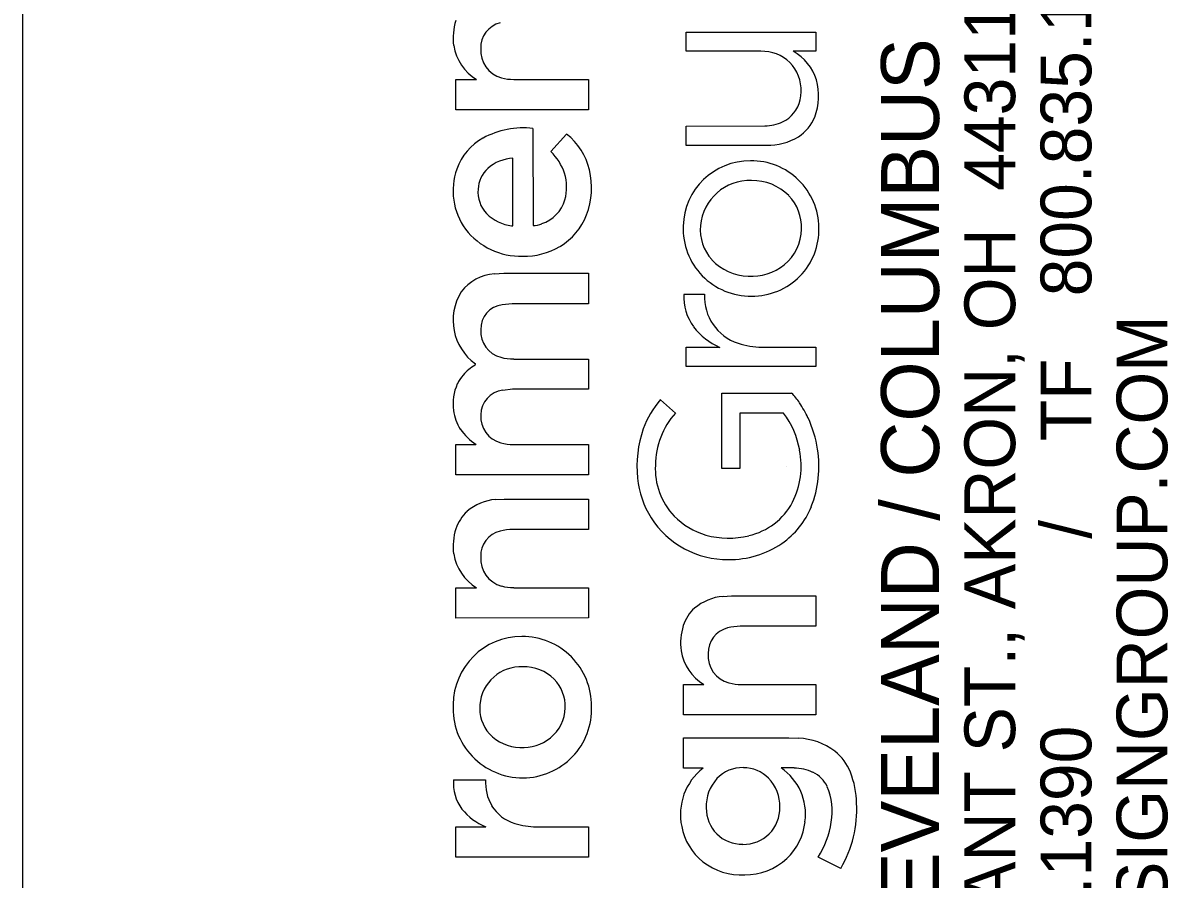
# Model space of a CAD drawing. Extents: x -4.2 to 34, y 0 to 22.
# Drawn here: x 32 to 33.125, y 3.594 to 4.436 of the extents above; entities that cross this region are included whole.
import ezdxf

# ---------------------------------------------------------------- set-up
doc = ezdxf.new("R2010")
doc.units = 0
doc.layers.add('SH_Border', color=7, linetype='Continuous')
doc.layers.add('SH_Data', color=7, linetype='Continuous')

msp = doc.modelspace()

# ---------------------------------------------------------------- linework, layer by layer
at = {"layer": 'SH_Border'}
msp.add_line((32, 0.5), (32, 21.5), dxfattribs=at)
at = {"layer": 'SH_Data'}
for p, q in [((32.6515, 4.408), (32.6515, 4.4267)), ((32.6515, 4.4267), (32.7791, 4.4266)), ((32.7791, 4.4266), (32.7791, 4.408)), ((32.7249, 4.408), (32.6515, 4.408)), ((32.7328, 4.4073), (32.7249, 4.408)), ((32.7791, 4.408), (32.7569, 4.408)), ((32.4254, 4.3503), (32.4254, 4.3802)), ((32.4254, 4.3802), (32.4455, 4.3802)), ((32.4822, 4.3802), (32.5557, 4.3802)), ((32.5557, 4.3802), (32.5557, 4.3504)), ((32.5557, 4.3504), (32.4254, 4.3503)), ((32.5011, 4.3321), (32.5012, 4.2366)), ((32.6515, 4.3344), (32.7291, 4.3345)), ((32.6517, 4.3154), (32.6515, 4.3344)), ((32.5188, 4.3093), (32.5342, 4.3266)), ((32.7307, 4.3154), (32.6517, 4.3154)), ((32.4814, 4.2364), (32.4814, 4.303)), ((32.4802, 4.2363), (32.4814, 4.2364)), ((32.4633, 4.1891), (32.4726, 4.1897)), ((32.4726, 4.1897), (32.5556, 4.1897)), ((32.5556, 4.1897), (32.5557, 4.1598)), ((32.6493, 4.1691), (32.6698, 4.1691)), ((32.4806, 4.1598), (32.471, 4.1588)), ((32.5557, 4.1598), (32.4806, 4.1598)), ((32.6515, 4.098), (32.6515, 4.117)), ((32.6515, 4.117), (32.6848, 4.117)), ((32.726, 4.117), (32.7791, 4.117)), ((32.7791, 4.117), (32.779, 4.098)), ((32.4444, 4.0992), (32.4446, 4.1007)), ((32.4822, 4.1055), (32.5557, 4.1055)), ((32.5557, 4.1055), (32.5557, 4.0757)), ((32.779, 4.098), (32.6515, 4.098)), ((32.4809, 4.0757), (32.4714, 4.0747)), ((32.5557, 4.0757), (32.4809, 4.0757)), ((32.6264, 4.0655), (32.6411, 4.0524)), ((32.6868, 4.0718), (32.7552, 4.0719)), ((32.6868, 3.9978), (32.6868, 4.0718)), ((32.7045, 4.0524), (32.7043, 3.9978)), ((32.7474, 4.0523), (32.7045, 4.0524)), ((32.4254, 3.9915), (32.4254, 4.0214)), ((32.4254, 4.0214), (32.4451, 4.0214)), ((32.4821, 4.0214), (32.5557, 4.0214)), ((32.5557, 4.0214), (32.5557, 3.9916)), ((32.7043, 3.9978), (32.6868, 3.9978)), ((32.75, 4), (32.75, 4)), ((32.5557, 3.9916), (32.4254, 3.9915)), ((32.4644, 3.9674), (32.4729, 3.9678)), ((32.4729, 3.9678), (32.5557, 3.9678)), ((32.5557, 3.9678), (32.5557, 3.938)), ((32.5557, 3.938), (32.4814, 3.938)), ((32.4254, 3.8509), (32.4254, 3.8807)), ((32.4254, 3.8807), (32.4455, 3.8807)), ((32.4822, 3.8807), (32.5557, 3.8807)), ((32.5557, 3.8807), (32.5557, 3.851)), ((32.6878, 3.8722), (32.6963, 3.8727)), ((32.6963, 3.8727), (32.7792, 3.8727)), ((32.7792, 3.8727), (32.7792, 3.8429)), ((32.5557, 3.851), (32.4254, 3.8509)), ((32.7792, 3.8429), (32.7048, 3.8428)), ((32.6489, 3.7557), (32.6489, 3.7855)), ((32.6489, 3.7855), (32.669, 3.7855)), ((32.7057, 3.7855), (32.7791, 3.7855)), ((32.7791, 3.7855), (32.7792, 3.7558)), ((32.7792, 3.7558), (32.6489, 3.7557)), ((32.6489, 3.7034), (32.6489, 3.7332)), ((32.6489, 3.7332), (32.7524, 3.7332)), ((32.7524, 3.7332), (32.7619, 3.7329)), ((32.6684, 3.7034), (32.6489, 3.7034)), ((32.7576, 3.7036), (32.7449, 3.7036)), ((32.423, 3.6919), (32.4545, 3.6919)), ((32.4254, 3.6159), (32.4254, 3.6458)), ((32.4254, 3.6458), (32.4547, 3.6458)), ((32.5041, 3.6458), (32.5557, 3.6457)), ((32.5557, 3.6457), (32.5556, 3.6159)), ((32.5556, 3.6159), (32.4254, 3.6159)), ((32.8036, 3.6049), (32.7812, 3.616))]:
    msp.add_line(p, q, dxfattribs=at)
for points in [[(32.7328, 4.4073), (32.7249, 4.408), (32.6515, 4.408), (32.6515, 4.4267), (32.7791, 4.4266), (32.7791, 4.408), (32.7569, 4.408)], [(32.4254, 4.3503), (32.4254, 4.3802), (32.4455, 4.3802)], [(32.4822, 4.3802), (32.5557, 4.3802), (32.5557, 4.3504), (32.4254, 4.3503)], [(32.5011, 4.3321), (32.5012, 4.2366)], [(32.7307, 4.3154), (32.6517, 4.3154), (32.6515, 4.3344), (32.7291, 4.3345)], [(32.5188, 4.3093), (32.5342, 4.3266)], [(32.4802, 4.2363), (32.4814, 4.2364), (32.4814, 4.303)], [(32.4633, 4.1891), (32.4726, 4.1897), (32.5556, 4.1897), (32.5557, 4.1598), (32.4806, 4.1598), (32.471, 4.1588)], [(32.6493, 4.1691), (32.6698, 4.1691)], [(32.6515, 4.098), (32.6515, 4.117), (32.6848, 4.117)], [(32.726, 4.117), (32.7791, 4.117), (32.779, 4.098), (32.6515, 4.098)], [(32.4444, 4.0992), (32.4446, 4.1007)], [(32.4822, 4.1055), (32.5557, 4.1055), (32.5557, 4.0757), (32.4809, 4.0757), (32.4714, 4.0747)], [(32.6264, 4.0655), (32.6411, 4.0524)], [(32.7474, 4.0523), (32.7045, 4.0524), (32.7043, 3.9978), (32.6868, 3.9978), (32.6868, 4.0718), (32.7552, 4.0719)], [(32.4254, 3.9915), (32.4254, 4.0214), (32.4451, 4.0214)], [(32.4821, 4.0214), (32.5557, 4.0214), (32.5557, 3.9916), (32.4254, 3.9915)], [(32.4644, 3.9674), (32.4729, 3.9678), (32.5557, 3.9678), (32.5557, 3.938), (32.4814, 3.938)], [(32.4254, 3.8509), (32.4254, 3.8807), (32.4455, 3.8807)], [(32.4822, 3.8807), (32.5557, 3.8807), (32.5557, 3.851), (32.4254, 3.8509)], [(32.6878, 3.8722), (32.6963, 3.8727), (32.7792, 3.8727), (32.7792, 3.8429), (32.7048, 3.8428)], [(32.6489, 3.7557), (32.6489, 3.7855), (32.669, 3.7855)], [(32.7057, 3.7855), (32.7791, 3.7855), (32.7792, 3.7558), (32.6489, 3.7557)], [(32.6684, 3.7034), (32.6489, 3.7034), (32.6489, 3.7332), (32.7524, 3.7332), (32.7619, 3.7329)], [(32.7576, 3.7036), (32.7449, 3.7036)], [(32.423, 3.6919), (32.4545, 3.6919)], [(32.4254, 3.6159), (32.4254, 3.6458), (32.4547, 3.6458)], [(32.5041, 3.6458), (32.5557, 3.6457), (32.5556, 3.6159), (32.4254, 3.6159)], [(32.8036, 3.6049), (32.7812, 3.616)]]:
    msp.add_lwpolyline(points, dxfattribs=at)
for centre, radius, start, end in [((32.4787, 4.4211), 0.056, 162.274, 187.7917), ((32.4787, 4.4211), 0.056, 162.274, 187.7917), ((32.4748, 4.4116), 0.025, 103.6868, 182.214), ((32.4748, 4.4116), 0.025, 103.6868, 182.214), ((32.4703, 4.4209), 0.0476, 188.9646, 238.6987), ((32.4703, 4.4209), 0.0476, 188.9646, 238.6987), ((32.4774, 4.4085), 0.0276, 175.5844, 255.1382), ((32.4774, 4.4085), 0.0276, 175.5844, 255.1382), ((32.7271, 4.37), 0.0377, 33.5008, 81.3295), ((32.7271, 4.37), 0.0377, 33.5008, 81.3295), ((32.7324, 4.3648), 0.0496, 17.6221, 60.3897), ((32.7324, 4.3648), 0.0496, 17.6221, 60.3897), ((32.7241, 4.3695), 0.0405, 346.5618, 31.7539), ((32.7241, 4.3695), 0.0405, 346.5618, 31.7539), ((32.4818, 4.4224), 0.0421, 254.0891, 270.5284), ((32.4818, 4.4224), 0.0421, 254.0891, 270.5284), ((32.7234, 4.3641), 0.0584, 339.162, 15.6148), ((32.7234, 4.3641), 0.0584, 339.162, 15.6148), ((32.7337, 4.3662), 0.0304, 294.6321, 348.4863), ((32.7337, 4.3662), 0.0304, 294.6321, 348.4863), ((32.739, 4.359), 0.042, 303.1039, 338.1561), ((32.739, 4.359), 0.042, 303.1039, 338.1561), ((32.4918, 4.2487), 0.0839, 83.6212, 118.2845), ((32.4918, 4.2487), 0.0839, 83.6212, 118.2845), ((32.7275, 4.3808), 0.0463, 271.952, 294.0894), ((32.7275, 4.3808), 0.0463, 271.952, 294.0894), ((32.4789, 4.2737), 0.0558, 118.8294, 160.6224), ((32.4789, 4.2737), 0.0558, 118.8294, 160.6224), ((32.494, 4.2763), 0.0644, 13.5328, 51.3627), ((32.494, 4.2763), 0.0644, 13.5328, 51.3627), ((32.7321, 4.3726), 0.0571, 268.627, 301.4778), ((32.7321, 4.3726), 0.0571, 268.627, 301.4778), ((32.4803, 4.2702), 0.0549, 19.0387, 45.4432), ((32.4803, 4.2702), 0.0549, 19.0387, 45.4432), ((32.4844, 4.2607), 0.0424, 94.0131, 130.8806), ((32.4844, 4.2607), 0.0424, 94.0131, 130.8806), ((32.7143, 4.2348), 0.0655, 89.4821, 178.7775), ((32.7143, 4.2348), 0.0655, 89.4821, 178.7775), ((32.7158, 4.2341), 0.0662, 0.4227, 90.7613), ((32.7158, 4.2341), 0.0662, 0.4227, 90.7613), ((32.487, 4.2707), 0.0644, 160.5214, 215.7815), ((32.487, 4.2707), 0.0644, 160.5214, 215.7815), ((32.477, 4.2709), 0.0298, 132.9855, 177.1802), ((32.477, 4.2709), 0.0298, 132.9855, 177.1802), ((32.4872, 4.2743), 0.047, 344.6072, 17.0067), ((32.4872, 4.2743), 0.047, 344.6072, 17.0067), ((32.4829, 4.2738), 0.0758, 339.3543, 13.3771), ((32.4829, 4.2738), 0.0758, 339.3543, 13.3771), ((32.714, 4.2324), 0.0485, 87.6883, 175.017), ((32.714, 4.2324), 0.0485, 87.6883, 175.017), ((32.7166, 4.2304), 0.0505, 44.912, 90.7591), ((32.7166, 4.2304), 0.0505, 44.912, 90.7591), ((32.4782, 4.2697), 0.0311, 175.0014, 223.2876), ((32.4782, 4.2697), 0.0311, 175.0014, 223.2876), ((32.7196, 4.2345), 0.0455, 358.3228, 43.8349), ((32.7196, 4.2345), 0.0455, 358.3228, 43.8349), ((32.499, 4.2718), 0.035, 288.0108, 343.5536), ((32.499, 4.2718), 0.035, 288.0108, 343.5536), ((32.4855, 4.2783), 0.0423, 225.0645, 262.797), ((32.4855, 4.2783), 0.0423, 225.0645, 262.797), ((32.4955, 4.2698), 0.0626, 300.9439, 338.7322), ((32.4955, 4.2698), 0.0626, 300.9439, 338.7322), ((32.4891, 4.2752), 0.0687, 217.7434, 271.6561), ((32.4891, 4.2752), 0.0687, 217.7434, 271.6561), ((32.5013, 4.2568), 0.0202, 269.7004, 294.8729), ((32.5013, 4.2568), 0.0202, 269.7004, 294.8729), ((32.7148, 4.2334), 0.0661, 177.5373, 270.9452), ((32.7148, 4.2334), 0.0661, 177.5373, 270.9452), ((32.7108, 4.2331), 0.0453, 175.5147, 221.4205), ((32.7108, 4.2331), 0.0453, 175.5147, 221.4205), ((32.7167, 4.2327), 0.0654, 269.3083, 1.6791), ((32.7167, 4.2327), 0.0654, 269.3083, 1.6791), ((32.7193, 4.2337), 0.0457, 308.9038, 359.3095), ((32.7193, 4.2337), 0.0457, 308.9038, 359.3095), ((32.492, 4.277), 0.0706, 269.2053, 300.3357), ((32.492, 4.277), 0.0706, 269.2053, 300.3357), ((32.714, 4.2373), 0.0505, 222.6626, 268.3733), ((32.714, 4.2373), 0.0505, 222.6626, 268.3733), ((32.7157, 4.2386), 0.0518, 266.5531, 308.6725), ((32.7157, 4.2386), 0.0518, 266.5531, 308.6725), ((32.4664, 4.144), 0.0452, 93.9112, 142.3072), ((32.4664, 4.144), 0.0452, 93.9112, 142.3072), ((32.4759, 4.1437), 0.0532, 148.2879, 233.9556), ((32.4759, 4.1437), 0.0532, 148.2879, 233.9556), ((32.6988, 4.1666), 0.0495, 177.1621, 216.2802), ((32.6988, 4.1666), 0.0495, 177.1621, 216.2802), ((32.7173, 4.1664), 0.0476, 176.7699, 252.1504), ((32.7173, 4.1664), 0.0476, 176.7699, 252.1504), ((32.4738, 4.135), 0.024, 96.7576, 181.6251), ((32.4738, 4.135), 0.024, 96.7576, 181.6251), ((32.4758, 4.1324), 0.026, 175.8157, 256.1672), ((32.4758, 4.1324), 0.026, 175.8157, 256.1672), ((32.7098, 4.1755), 0.0637, 216.9153, 246.8862), ((32.7098, 4.1755), 0.0637, 216.9153, 246.8862), ((32.7269, 4.1917), 0.0747, 251.1388, 269.3469), ((32.7269, 4.1917), 0.0747, 251.1388, 269.3469), ((32.4817, 4.1505), 0.045, 254.3463, 270.6103), ((32.4817, 4.1505), 0.045, 254.3463, 270.6103), ((32.4638, 4.0627), 0.0414, 117.9163, 139.243), ((32.4638, 4.0627), 0.0414, 117.9163, 139.243), ((32.4619, 4.0645), 0.0387, 139.5245, 154.847), ((32.4619, 4.0645), 0.0387, 139.5245, 154.847), ((32.4714, 4.0612), 0.0488, 156.0638, 187.3493), ((32.4714, 4.0612), 0.0488, 156.0638, 187.3493), ((32.4742, 4.0506), 0.0243, 96.5532, 179.949), ((32.4742, 4.0506), 0.0243, 96.5532, 179.949), ((32.7016, 4.0019), 0.0986, 139.7948, 159.137), ((32.7016, 4.0019), 0.0986, 139.7948, 159.137), ((32.725, 4.0394), 0.0444, 30.9891, 47.161), ((32.725, 4.0394), 0.0444, 30.9891, 47.161), ((32.6709, 4.0002), 0.1111, 25.3031, 33.9618), ((32.6709, 4.0002), 0.1111, 25.3031, 33.9618), ((32.4646, 4.0597), 0.0418, 186.5579, 213.3885), ((32.4646, 4.0597), 0.0418, 186.5579, 213.3885), ((32.4761, 4.0486), 0.0263, 175.722, 255.7863), ((32.4761, 4.0486), 0.0263, 175.722, 255.7863), ((32.699, 4.0008), 0.0775, 138.258, 179.7006), ((32.699, 4.0008), 0.0775, 138.258, 179.7006), ((32.6789, 4.001), 0.0856, 10.0751, 36.8319), ((32.6789, 4.001), 0.0856, 10.0751, 36.8319), ((32.6704, 3.9999), 0.1117, 8.8034, 25.3348), ((32.6704, 3.9999), 0.1117, 8.8034, 25.3348), ((32.4789, 4.0708), 0.0598, 214.7043, 235.6872), ((32.4789, 4.0708), 0.0598, 214.7043, 235.6872), ((32.7187, 3.9997), 0.1154, 161.1438, 185.6281), ((32.7187, 3.9997), 0.1154, 161.1438, 185.6281), ((32.4819, 4.0652), 0.0438, 253.6672, 270.1498), ((32.4819, 4.0652), 0.0438, 253.6672, 270.1498), ((32.6756, 3.9998), 0.1065, 338.2887, 9.2855), ((32.6756, 3.9998), 0.1065, 338.2887, 9.2855), ((32.6842, 4.0006), 0.0804, 333.4669, 11.0367), ((32.6842, 4.0006), 0.0804, 333.4669, 11.0367), ((32.6881, 3.9973), 0.0668, 176.6658, 223.6912), ((32.6881, 3.9973), 0.0668, 176.6658, 223.6912), ((32.6934, 3.997), 0.0899, 185.5077, 212.0129), ((32.6934, 3.997), 0.0899, 185.5077, 212.0129), ((32.4687, 3.9177), 0.0499, 94.9706, 130.2248), ((32.4687, 3.9177), 0.0499, 94.9706, 130.2248), ((32.6987, 3.9955), 0.0652, 282.8815, 331.8147), ((32.6987, 3.9955), 0.0652, 282.8815, 331.8147), ((32.4635, 3.926), 0.0402, 132.2238, 161.6823), ((32.4635, 3.926), 0.0402, 132.2238, 161.6823), ((32.6921, 3.9975), 0.0891, 212.7022, 270.714), ((32.6921, 3.9975), 0.0891, 212.7022, 270.714), ((32.6905, 4.0001), 0.0704, 224.0215, 253.88), ((32.6905, 4.0001), 0.0704, 224.0215, 253.88), ((32.6984, 3.9917), 0.0824, 305.0306, 337.6757), ((32.6984, 3.9917), 0.0824, 305.0306, 337.6757), ((32.4787, 3.9216), 0.056, 162.274, 187.7917), ((32.4787, 3.9216), 0.056, 162.274, 187.7917), ((32.4748, 3.9121), 0.025, 103.6868, 182.214), ((32.4748, 3.9121), 0.025, 103.6868, 182.214), ((32.4811, 3.892), 0.046, 89.6051, 105.3303), ((32.4811, 3.892), 0.046, 89.6051, 105.3303), ((32.6932, 4.0125), 0.0831, 254.4535, 283.9512), ((32.6932, 4.0125), 0.0831, 254.4535, 283.9512), ((32.6943, 3.9998), 0.0914, 269.3273, 304.1963), ((32.6943, 3.9998), 0.0914, 269.3273, 304.1963), ((32.4703, 3.9214), 0.0476, 188.9646, 238.6987), ((32.4703, 3.9214), 0.0476, 188.9646, 238.6987), ((32.4774, 3.909), 0.0276, 175.5844, 255.1382), ((32.4774, 3.909), 0.0276, 175.5844, 255.1382), ((32.4818, 3.9229), 0.0421, 254.0891, 270.5284), ((32.4818, 3.9229), 0.0421, 254.0891, 270.5284), ((32.6922, 3.8225), 0.0499, 94.9706, 130.2248), ((32.6922, 3.8225), 0.0499, 94.9706, 130.2248), ((32.6869, 3.8309), 0.0402, 132.2238, 161.6823), ((32.6869, 3.8309), 0.0402, 132.2238, 161.6823), ((32.7022, 3.8264), 0.056, 162.274, 187.7917), ((32.7022, 3.8264), 0.056, 162.274, 187.7917), ((32.6983, 3.8169), 0.025, 103.6868, 182.214), ((32.6983, 3.8169), 0.025, 103.6868, 182.214), ((32.7045, 3.7968), 0.046, 89.6051, 105.3303), ((32.7045, 3.7968), 0.046, 89.6051, 105.3303), ((32.4901, 3.7654), 0.0674, 89.8476, 179.6405), ((32.4901, 3.7654), 0.0674, 89.8476, 179.6405), ((32.4906, 3.7647), 0.0681, 359.5401, 90.2114), ((32.4906, 3.7647), 0.0681, 359.5401, 90.2114), ((32.6937, 3.8262), 0.0476, 188.9646, 238.6987), ((32.6937, 3.8262), 0.0476, 188.9646, 238.6987), ((32.7008, 3.8138), 0.0276, 175.5844, 255.1382), ((32.7008, 3.8138), 0.0276, 175.5844, 255.1382), ((32.4892, 3.7626), 0.0404, 87.0481, 175.5726), ((32.4892, 3.7626), 0.0404, 87.0481, 175.5726), ((32.492, 3.76), 0.043, 45.8426, 90.9801), ((32.492, 3.76), 0.043, 45.8426, 90.9801), ((32.4946, 3.7642), 0.0382, 357.8857, 44.159), ((32.4946, 3.7642), 0.0382, 357.8857, 44.159), ((32.7053, 3.8277), 0.0421, 254.0891, 270.5284), ((32.7053, 3.8277), 0.0421, 254.0891, 270.5284), ((32.4908, 3.7621), 0.0682, 176.8344, 270.4038), ((32.4908, 3.7621), 0.0682, 176.8344, 270.4038), ((32.4873, 3.7625), 0.0385, 175.1538, 221.1471), ((32.4873, 3.7625), 0.0385, 175.1538, 221.1471), ((32.4912, 3.7614), 0.0675, 270.0624, 2.3776), ((32.4912, 3.7614), 0.0675, 270.0624, 2.3776), ((32.4945, 3.7632), 0.0383, 308.2894, 359.4347), ((32.4945, 3.7632), 0.0383, 308.2894, 359.4347), ((32.4892, 3.7661), 0.0423, 223.0999, 268.8089), ((32.4892, 3.7661), 0.0423, 223.0999, 268.8089), ((32.491, 3.7679), 0.0442, 266.5651, 308.0608), ((32.491, 3.7679), 0.0442, 266.5651, 308.0608), ((32.7591, 3.6679), 0.065, 53.4034, 87.4906), ((32.7591, 3.6679), 0.065, 53.4034, 87.4906), ((32.7652, 3.6804), 0.0514, 21.6075, 50.5577), ((32.7652, 3.6804), 0.0514, 21.6075, 50.5577), ((32.7029, 3.6581), 0.0569, 127.3748, 192.2247), ((32.7029, 3.6581), 0.0569, 127.3748, 192.2247), ((32.7069, 3.6693), 0.0346, 88.473, 136.4256), ((32.7069, 3.6693), 0.0346, 88.473, 136.4256), ((32.7081, 3.6696), 0.0342, 44.2719, 90.4762), ((32.7081, 3.6696), 0.0342, 44.2719, 90.4762), ((32.7142, 3.6583), 0.0547, 352.1125, 55.923), ((32.7142, 3.6583), 0.0547, 352.1125, 55.923), ((32.7567, 3.6572), 0.0463, 65.0169, 88.8011), ((32.7567, 3.6572), 0.0463, 65.0169, 88.8011), ((32.4662, 3.6888), 0.0433, 175.8731, 216.3475), ((32.4662, 3.6888), 0.0433, 175.8731, 216.3475), ((32.5009, 3.6895), 0.0464, 176.9688, 209.6064), ((32.5009, 3.6895), 0.0464, 176.9688, 209.6064), ((32.7114, 3.666), 0.0401, 137.4674, 182.3324), ((32.7114, 3.666), 0.0401, 137.4674, 182.3324), ((32.7037, 3.666), 0.04, 358.5714, 43.5376), ((32.7037, 3.666), 0.04, 358.5714, 43.5376), ((32.7626, 3.6716), 0.0309, 26.2681, 63.803), ((32.7626, 3.6716), 0.0309, 26.2681, 63.803), ((32.7307, 3.6671), 0.0884, 1.1514, 21.3627), ((32.7307, 3.6671), 0.0884, 1.1514, 21.3627), ((32.7357, 3.6615), 0.0595, 349.3073, 23.4307), ((32.7357, 3.6615), 0.0595, 349.3073, 23.4307), ((32.7054, 3.6624), 0.1138, 329.6388, 3.26), ((32.7054, 3.6624), 0.1138, 329.6388, 3.26), ((32.4747, 3.6972), 0.0551, 218.0981, 248.7907), ((32.4747, 3.6972), 0.0551, 218.0981, 248.7907), ((32.4951, 3.6881), 0.0408, 211.9447, 253.2028), ((32.4951, 3.6881), 0.0408, 211.9447, 253.2028), ((32.7065, 3.6637), 0.0351, 178.8821, 271.0837), ((32.7065, 3.6637), 0.0351, 178.8821, 271.0837), ((32.7082, 3.664), 0.0355, 268.2788, 1.5502), ((32.7082, 3.664), 0.0355, 268.2788, 1.5502), ((32.5047, 3.7165), 0.0707, 252.4655, 269.573), ((32.5047, 3.7165), 0.0707, 252.4655, 269.573), ((32.7046, 3.657), 0.0584, 190.7518, 231.2892), ((32.7046, 3.657), 0.0584, 190.7518, 231.2892), ((32.7099, 3.6571), 0.0589, 313.742, 353.8554), ((32.7099, 3.6571), 0.0589, 313.742, 353.8554), ((32.7074, 3.6633), 0.0877, 327.3149, 351.5748), ((32.7074, 3.6633), 0.0877, 327.3149, 351.5748), ((32.7095, 3.659), 0.0605, 269.6361, 312.7088), ((32.7095, 3.659), 0.0605, 269.6361, 312.7088), ((32.7063, 3.6611), 0.0627, 232.4606, 272.5902), ((32.7063, 3.6611), 0.0627, 232.4606, 272.5902)]:
    msp.add_arc(centre, radius, start, end, dxfattribs=at)

# ---------------------------------------------------------------- texts
for s, height, p in [('800.835.1390', 0.049846, (33.0497, 4.1671)), ('450 GRANT ST., AKRON, OH  44311', 0.049846, (32.9749, 3.3374)), ('AKRON / CLEVELAND / COLUMBUS', 0.056969, (32.9001, 3.138)), ('ENVDESIGNGROUP.COM', 0.049846, (33.1244, 3.3374)), ('TF', 0.04985, (33.0497, 4.0246)), ('/  ', 0.04985, (33.0497, 3.9288)), ('330.375.1390', 0.049846, (33.0497, 3.3374))]:
    msp.add_text(s, height=height, rotation=90, dxfattribs=at).set_placement(p)

doc.saveas('drawing.dxf')
